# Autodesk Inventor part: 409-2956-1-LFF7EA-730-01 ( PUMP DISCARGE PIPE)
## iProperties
Created: 2010-06
Part Number: 409-2956-1-LFF7EA-730-01 ( PUMP DISCARGE PIPE)
Material: Sch40 CS PIPE SEAMLESS
Description: PIPE
Document SubType Name: Modeling
Designer: S. Boerckel
Engineer: Steve Boerckel
Mass: 932.253 g
Surface Area: 655.215 cm^2
Volume: 118.758 cm^3
Density: 7.85 g/cm^3
Cost Center: 1-1/2"
SMR: =<COST CENTER> - <Material>
Length: 9.065 in
Title: 1-1/2"
Author: S. Boerckel
Revision Number: A
Subject: DEMIN WATER FORWARDING PUMP SKID-7EA
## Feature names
1. Extrusion1
